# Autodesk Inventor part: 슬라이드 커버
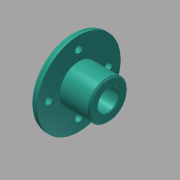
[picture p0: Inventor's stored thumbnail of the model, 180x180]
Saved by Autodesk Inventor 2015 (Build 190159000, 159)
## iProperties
Created: 2015-12
Part Number: 슬라이드 커버
Document SubType Name: Modeling
Designer: mdu
Density: 2.71 g/cm^3
Material: 알루미늄 6061
Mass: 49.5723 g
Surface Area: 80.7135 cm^2
Volume: 18.2924 cm^3
Appearance: 알루미늄 - 평지
Author: mdu
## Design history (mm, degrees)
sketch "스케치1"
  geometry: L1 (-12.5, 0)-(12.5, 0); L2 (-12.5, 0)-(-12.5, 28); L3 (-12.5, 28)-(-7.5, 28); L4 (-7.5, 28)-(-7.5, 13); L5 (-7.5, 13)-(12.5, 13); L6 (12.5, 13)-(12.5, 0); 2 further points
  constraints: 12 end point, 3 perpendicular, 1 coincident, 1 horizontal, 1 midpoint, 1 parallel
  dimensions: "d1" = 56 diameter of L3 L1; "d2" = 26 diameter of L5 L1; "d5" = 5 distance of L2.end L3.end; "d32" = 20 distance of L4.end L5.end
revolve "회전1" sketch "스케치1" stored, may be unused: angle "d6" = 90 deg
sketch "스케치2" dims "d33" = 40
  geometry: 3 further points
  constraints: 2 vertical alignment, 1 coincident, 2 other
hole "구멍1" sketch "스케치2" at (0, 20) diameter "d8" = 5; stored, may be unused: countersink angle "d12" = 90 deg, drill point angle "d14" = 118 deg; dims "d9" = 6, "d10" = 8, "d11" = 4.4, "d13" = 8
hole "구멍2" diameter "d20" = 14; stored, may be unused: countersink angle "d24" = 90 deg, drill point angle "d26" = 0 deg; dims "d18" = 10, "d19" = 10, "d21" = 6, "d22" = 8, "d23" = 4.4, "d25" = 8
fillet "모깎기1" dims "d27" = 3
chamfer "모따기1" distance "d29" = 1; stored, may be unused: second distance "d30" = 2, angle "d31" = 45 deg
chamfer "모따기2" distance "d35" = 0.5; stored, may be unused: second distance "d36" = 2, angle "d37" = 45 deg
node "솔리드1"
pattern_circular "원형 패턴1" dims angle "d16" = 360 deg
